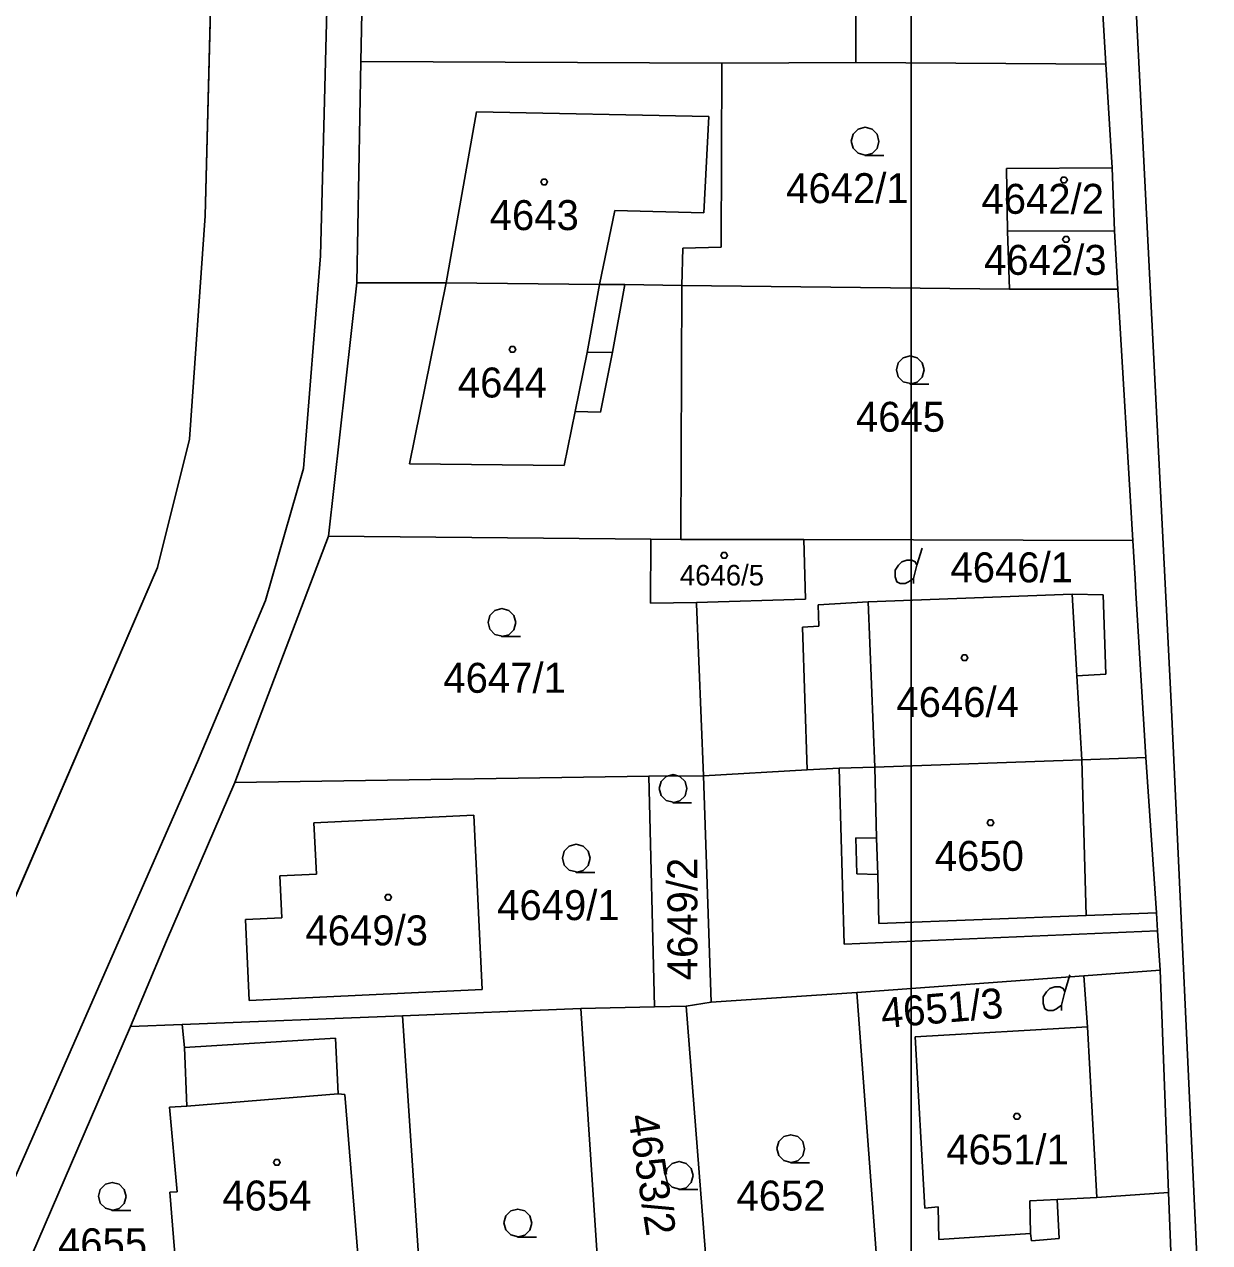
# Model space of a CAD drawing. Extents: x -263587 to -261993, y -1238795 to -1236748.
# Drawn here: x -262742.4 to -262679.1, y -1237619.9 to -1237554.8 of the extents above; entities that cross this region are included whole.
import ezdxf

# ---------------------------------------------------------------- set-up
doc = ezdxf.new("R2010")
doc.units = 0
for name, color, linetype in [('Vrstva 1', 7, 'Continuous'), ('Vrstva 2', 7, 'Continuous'), ('Vrstva 3', 7, 'Continuous'), ('Vrstva 51', 7, 'Continuous')]:
    doc.layers.add(name, color=color, linetype=linetype)

msp = doc.modelspace()

# ---------------------------------------------------------------- linework, layer by layer
at = {"layer": 'Vrstva 1'}
for p, q in [((-262725.22, -1237515.08), (-262726.58, -1237567.18)), ((-262684.42, -1237526.68), (-262682.75, -1237559.3)), ((-262685.72, -1237539.5), (-262684.63, -1237556.95)), ((-262684.63, -1237556.95), (-262685.72, -1237539.5)), ((-262724.42, -1237556.81), (-262724.09, -1237539.86)), ((-262724.09, -1237539.86), (-262724.42, -1237556.81)), ((-262732.74, -1237565.04), (-262732.21, -1237544.17)), ((-262732.21, -1237544.17), (-262732.74, -1237565.04)), ((-262697.98, -1237556.86), (-262697.99, -1237549)), ((-262697.99, -1237549), (-262697.98, -1237556.86)), ((-262724.64, -1237568.62), (-262724.42, -1237556.81)), ((-262724.42, -1237556.81), (-262724.64, -1237568.62)), ((-262705.15, -1237556.89), (-262724.42, -1237556.81)), ((-262724.42, -1237556.81), (-262705.15, -1237556.89)), ((-262705.18, -1237566.72), (-262705.15, -1237556.89)), ((-262705.15, -1237556.89), (-262705.18, -1237566.72)), ((-262705.15, -1237556.89), (-262697.98, -1237556.86)), ((-262697.98, -1237556.86), (-262705.15, -1237556.89)), ((-262684.63, -1237556.95), (-262697.98, -1237556.86)), ((-262697.98, -1237556.86), (-262684.63, -1237556.95)), ((-262684.63, -1237556.95), (-262684.29, -1237562.48)), ((-262684.29, -1237562.48), (-262684.63, -1237556.95)), ((-262682.75, -1237559.3), (-262681.14, -1237591.03)), ((-262718.25, -1237559.49), (-262719.87, -1237568.62)), ((-262705.83, -1237559.74), (-262718.25, -1237559.49)), ((-262706.1, -1237564.89), (-262705.83, -1237559.74)), ((-262689.94, -1237562.52), (-262684.29, -1237562.48)), ((-262684.29, -1237562.48), (-262689.94, -1237562.52)), ((-262689.89, -1237565.87), (-262689.94, -1237562.52)), ((-262689.94, -1237562.52), (-262689.89, -1237565.87)), ((-262684.29, -1237562.48), (-262684.17, -1237565.85)), ((-262684.17, -1237565.85), (-262684.29, -1237562.48)), ((-262733.58, -1237576.98), (-262732.74, -1237565.04)), ((-262732.74, -1237565.04), (-262733.58, -1237576.98)), ((-262711.67, -1237568.71), (-262710.85, -1237564.77)), ((-262710.85, -1237564.77), (-262706.1, -1237564.89)), ((-262689.89, -1237565.87), (-262684.17, -1237565.85)), ((-262684.17, -1237565.85), (-262689.89, -1237565.87)), ((-262689.78, -1237568.97), (-262689.89, -1237565.87)), ((-262689.89, -1237565.87), (-262689.78, -1237568.97)), ((-262684.17, -1237565.85), (-262683.99, -1237568.97)), ((-262683.99, -1237568.97), (-262684.17, -1237565.85)), ((-262707.28, -1237568.76), (-262707.23, -1237566.78)), ((-262707.23, -1237566.78), (-262707.28, -1237568.76)), ((-262707.23, -1237566.78), (-262705.18, -1237566.72)), ((-262705.18, -1237566.72), (-262707.23, -1237566.78)), ((-262726.58, -1237567.18), (-262727.48, -1237578.54)), ((-262726.16, -1237582.16), (-262724.64, -1237568.62)), ((-262724.64, -1237568.62), (-262726.16, -1237582.16)), ((-262724.64, -1237568.62), (-262719.87, -1237568.62)), ((-262719.87, -1237568.62), (-262724.64, -1237568.62)), ((-262719.87, -1237568.62), (-262721.82, -1237578.3)), ((-262719.87, -1237568.62), (-262711.67, -1237568.71)), ((-262711.67, -1237568.71), (-262719.87, -1237568.62)), ((-262711.67, -1237568.71), (-262712.33, -1237572.34)), ((-262711.67, -1237568.71), (-262710.33, -1237568.72)), ((-262710.33, -1237568.72), (-262711.67, -1237568.71)), ((-262710.33, -1237568.72), (-262710.99, -1237572.32)), ((-262710.33, -1237568.72), (-262707.28, -1237568.76)), ((-262707.28, -1237568.76), (-262710.33, -1237568.72)), ((-262707.33, -1237582.33), (-262707.28, -1237568.76)), ((-262707.28, -1237568.76), (-262707.33, -1237582.33)), ((-262707.28, -1237568.76), (-262689.78, -1237568.97)), ((-262689.78, -1237568.97), (-262707.28, -1237568.76)), ((-262689.78, -1237568.97), (-262683.99, -1237568.97)), ((-262683.99, -1237568.97), (-262689.78, -1237568.97)), ((-262683.99, -1237568.97), (-262683.19, -1237582.38)), ((-262683.19, -1237582.38), (-262683.99, -1237568.97)), ((-262712.33, -1237572.34), (-262710.99, -1237572.32)), ((-262710.99, -1237572.32), (-262711.62, -1237575.53)), ((-262712.98, -1237575.49), (-262712.33, -1237572.34)), ((-262713.56, -1237578.39), (-262712.98, -1237575.49)), ((-262711.62, -1237575.53), (-262712.98, -1237575.49)), ((-262735.28, -1237583.83), (-262733.58, -1237576.98)), ((-262733.58, -1237576.98), (-262735.28, -1237583.83)), ((-262727.48, -1237578.54), (-262729.52, -1237585.6)), ((-262721.82, -1237578.3), (-262713.56, -1237578.39)), ((-262726.16, -1237582.16), (-262731.16, -1237595.31)), ((-262731.16, -1237595.31), (-262726.16, -1237582.16)), ((-262708.93, -1237582.32), (-262726.16, -1237582.16)), ((-262726.16, -1237582.16), (-262708.93, -1237582.32)), ((-262708.93, -1237582.32), (-262708.96, -1237585.73)), ((-262708.96, -1237585.73), (-262708.93, -1237582.32)), ((-262707.33, -1237582.33), (-262708.93, -1237582.32)), ((-262708.93, -1237582.32), (-262707.33, -1237582.33)), ((-262706.63, -1237582.33), (-262707.33, -1237582.33)), ((-262707.33, -1237582.33), (-262706.63, -1237582.33)), ((-262700.76, -1237582.34), (-262706.63, -1237582.33)), ((-262706.63, -1237582.33), (-262700.76, -1237582.34)), ((-262683.19, -1237582.38), (-262700.76, -1237582.34)), ((-262700.67, -1237585.52), (-262700.76, -1237582.34)), ((-262700.76, -1237582.34), (-262683.19, -1237582.38)), ((-262700.76, -1237582.34), (-262700.67, -1237585.52)), ((-262683.07, -1237584.44), (-262683.19, -1237582.38)), ((-262683.19, -1237582.38), (-262683.07, -1237584.44)), ((-262694.72, -1237583.7), (-262694.45, -1237582.8)), ((-262745.26, -1237606.9), (-262735.28, -1237583.83)), ((-262735.28, -1237583.83), (-262745.26, -1237606.9)), ((-262683.03, -1237585.18), (-262683.07, -1237584.44)), ((-262683.07, -1237584.44), (-262683.03, -1237585.18)), ((-262697.33, -1237585.67), (-262686.43, -1237585.26)), ((-262686.43, -1237585.26), (-262697.33, -1237585.67)), ((-262686.43, -1237585.26), (-262684.78, -1237585.28)), ((-262684.78, -1237585.28), (-262686.43, -1237585.26)), ((-262686.43, -1237585.26), (-262686.18, -1237589.62)), ((-262684.78, -1237585.28), (-262684.63, -1237589.53)), ((-262684.63, -1237589.53), (-262684.78, -1237585.28)), ((-262682.49, -1237593.98), (-262683.03, -1237585.18)), ((-262683.03, -1237585.18), (-262682.49, -1237593.98)), ((-262729.52, -1237585.6), (-262733.15, -1237594.2)), ((-262708.96, -1237585.73), (-262706.49, -1237585.69)), ((-262706.49, -1237585.69), (-262708.96, -1237585.73)), ((-262706.49, -1237585.69), (-262700.67, -1237585.52)), ((-262700.67, -1237585.52), (-262706.49, -1237585.69)), ((-262706.49, -1237585.77), (-262706.49, -1237585.69)), ((-262706.49, -1237585.69), (-262706.49, -1237585.77)), ((-262706.13, -1237594.95), (-262706.49, -1237585.77)), ((-262706.49, -1237585.77), (-262706.13, -1237594.95)), ((-262700, -1237585.82), (-262697.33, -1237585.67)), ((-262697.33, -1237585.67), (-262700, -1237585.82)), ((-262699.97, -1237586.97), (-262700, -1237585.82)), ((-262700, -1237585.82), (-262699.97, -1237586.97)), ((-262697.33, -1237585.67), (-262696.98, -1237594.49)), ((-262700.84, -1237587.01), (-262699.97, -1237586.97)), ((-262699.97, -1237586.97), (-262700.84, -1237587.01)), ((-262700.59, -1237594.64), (-262700.84, -1237587.01)), ((-262700.84, -1237587.01), (-262700.59, -1237594.64)), ((-262684.63, -1237589.53), (-262686.18, -1237589.62)), ((-262686.18, -1237589.62), (-262684.63, -1237589.53)), ((-262686.18, -1237589.62), (-262685.92, -1237594.1)), ((-262685.92, -1237594.1), (-262686.18, -1237589.62)), ((-262681.14, -1237591.03), (-262679.09, -1237635.62)), ((-262733.15, -1237594.2), (-262745.42, -1237622.14)), ((-262696.98, -1237594.49), (-262685.92, -1237594.1)), ((-262685.92, -1237594.1), (-262696.98, -1237594.49)), ((-262685.92, -1237594.1), (-262682.49, -1237593.98)), ((-262682.49, -1237593.98), (-262685.92, -1237594.1)), ((-262685.92, -1237594.1), (-262685.69, -1237602.42)), ((-262682.49, -1237593.98), (-262681.93, -1237602.28)), ((-262681.93, -1237602.28), (-262682.49, -1237593.98)), ((-262731.16, -1237595.31), (-262709.04, -1237594.97)), ((-262709.04, -1237594.97), (-262731.16, -1237595.31)), ((-262709.04, -1237594.97), (-262706.13, -1237594.95)), ((-262706.13, -1237594.95), (-262709.04, -1237594.97)), ((-262709.04, -1237594.97), (-262708.74, -1237607.3)), ((-262708.74, -1237607.3), (-262709.04, -1237594.97)), ((-262706.13, -1237594.95), (-262700.59, -1237594.64)), ((-262700.59, -1237594.64), (-262706.13, -1237594.95)), ((-262705.72, -1237607.05), (-262706.13, -1237594.95)), ((-262706.13, -1237594.95), (-262705.72, -1237607.05)), ((-262700.59, -1237594.64), (-262698.87, -1237594.55)), ((-262698.87, -1237594.55), (-262700.59, -1237594.64)), ((-262698.87, -1237594.55), (-262696.98, -1237594.49)), ((-262696.98, -1237594.49), (-262698.87, -1237594.55)), ((-262698.61, -1237603.95), (-262698.87, -1237594.55)), ((-262696.98, -1237594.49), (-262696.88, -1237598.29)), ((-262731.16, -1237595.31), (-262734.81, -1237603.76)), ((-262734.81, -1237603.76), (-262731.16, -1237595.31)), ((-262718.39, -1237597.05), (-262726.93, -1237597.46)), ((-262726.93, -1237597.46), (-262718.39, -1237597.05)), ((-262717.94, -1237606.36), (-262718.39, -1237597.05)), ((-262718.39, -1237597.05), (-262717.94, -1237606.36)), ((-262726.93, -1237597.46), (-262726.8, -1237600.2)), ((-262726.8, -1237600.2), (-262726.93, -1237597.46)), ((-262697.94, -1237600.19), (-262697.98, -1237598.27)), ((-262697.98, -1237598.27), (-262696.88, -1237598.29)), ((-262696.88, -1237598.29), (-262696.82, -1237600.22)), ((-262726.8, -1237600.2), (-262728.75, -1237600.29)), ((-262728.75, -1237600.29), (-262726.8, -1237600.2)), ((-262728.75, -1237600.29), (-262728.64, -1237602.54)), ((-262728.64, -1237602.54), (-262728.75, -1237600.29)), ((-262696.82, -1237600.22), (-262697.94, -1237600.19)), ((-262696.82, -1237600.22), (-262696.75, -1237602.85)), ((-262728.64, -1237602.54), (-262730.59, -1237602.63)), ((-262730.59, -1237602.63), (-262728.64, -1237602.54)), ((-262730.59, -1237602.63), (-262730.39, -1237606.96)), ((-262730.39, -1237606.96), (-262730.59, -1237602.63)), ((-262696.75, -1237602.85), (-262685.69, -1237602.42)), ((-262685.69, -1237602.42), (-262681.93, -1237602.28)), ((-262681.93, -1237602.28), (-262681.87, -1237603.23)), ((-262681.87, -1237603.23), (-262681.93, -1237602.28)), ((-262681.87, -1237603.23), (-262698.61, -1237603.95)), ((-262681.87, -1237603.23), (-262681.73, -1237605.33)), ((-262681.73, -1237605.33), (-262681.87, -1237603.23)), ((-262734.81, -1237603.76), (-262736.72, -1237608.35)), ((-262736.72, -1237608.35), (-262734.81, -1237603.76)), ((-262681.73, -1237605.33), (-262685.81, -1237605.63)), ((-262685.81, -1237605.63), (-262681.73, -1237605.33)), ((-262681.73, -1237605.33), (-262681.28, -1237617.21)), ((-262681.28, -1237617.21), (-262681.73, -1237605.33)), ((-262685.81, -1237605.63), (-262697.94, -1237606.53)), ((-262697.94, -1237606.53), (-262685.81, -1237605.63)), ((-262686.82, -1237606.49), (-262686.55, -1237605.59)), ((-262685.62, -1237608.36), (-262685.81, -1237605.63)), ((-262730.39, -1237606.96), (-262717.94, -1237606.36)), ((-262717.94, -1237606.36), (-262730.39, -1237606.96)), ((-262697.94, -1237606.53), (-262705.72, -1237607.05)), ((-262705.72, -1237607.05), (-262697.94, -1237606.53)), ((-262696.5, -1237625.67), (-262697.94, -1237606.53)), ((-262697.94, -1237606.53), (-262696.5, -1237625.67)), ((-262722.2, -1237607.78), (-262712.67, -1237607.38)), ((-262712.67, -1237607.38), (-262722.2, -1237607.78)), ((-262712.67, -1237607.38), (-262708.74, -1237607.3)), ((-262708.74, -1237607.3), (-262712.67, -1237607.38)), ((-262712.67, -1237607.38), (-262711.37, -1237627.29)), ((-262711.37, -1237627.29), (-262712.67, -1237607.38)), ((-262708.74, -1237607.3), (-262707.05, -1237607.25)), ((-262707.05, -1237607.25), (-262708.74, -1237607.3)), ((-262707.05, -1237607.25), (-262705.72, -1237607.05)), ((-262705.72, -1237607.05), (-262707.05, -1237607.25)), ((-262705.54, -1237626.61), (-262707.05, -1237607.25)), ((-262707.05, -1237607.25), (-262705.54, -1237626.61)), ((-262733.96, -1237608.23), (-262722.2, -1237607.78)), ((-262722.2, -1237607.78), (-262733.96, -1237608.23)), ((-262722.2, -1237607.78), (-262720.83, -1237628.38)), ((-262720.83, -1237628.38), (-262722.2, -1237607.78)), ((-262742.95, -1237622.74), (-262736.72, -1237608.35)), ((-262736.72, -1237608.35), (-262742.95, -1237622.74)), ((-262736.72, -1237608.35), (-262733.96, -1237608.23)), ((-262733.96, -1237608.23), (-262736.72, -1237608.35)), ((-262733.84, -1237609.46), (-262733.96, -1237608.23)), ((-262733.96, -1237608.23), (-262733.84, -1237609.46)), ((-262685.62, -1237608.36), (-262694.81, -1237608.89)), ((-262694.81, -1237608.89), (-262685.62, -1237608.36)), ((-262685.12, -1237617.47), (-262685.62, -1237608.36)), ((-262685.62, -1237608.36), (-262685.12, -1237617.47)), ((-262733.84, -1237609.46), (-262725.77, -1237608.97)), ((-262725.77, -1237608.97), (-262725.64, -1237611.94)), ((-262694.81, -1237608.89), (-262694.31, -1237618.04)), ((-262694.31, -1237618.04), (-262694.81, -1237608.89)), ((-262733.71, -1237612.59), (-262733.84, -1237609.46)), ((-262733.84, -1237609.46), (-262733.71, -1237612.59)), ((-262733.71, -1237612.59), (-262725.64, -1237611.94)), ((-262725.64, -1237611.94), (-262725.28, -1237611.97)), ((-262725.28, -1237611.97), (-262724.4, -1237622.64)), ((-262734.65, -1237612.65), (-262733.71, -1237612.59)), ((-262733.71, -1237612.59), (-262734.65, -1237612.65)), ((-262734.23, -1237617.17), (-262734.65, -1237612.65)), ((-262734.65, -1237612.65), (-262734.23, -1237617.17)), ((-262734.62, -1237617.19), (-262734.23, -1237617.17)), ((-262734.23, -1237617.17), (-262734.62, -1237617.19)), ((-262734.23, -1237622.09), (-262734.62, -1237617.19)), ((-262734.62, -1237617.19), (-262734.23, -1237622.09)), ((-262685.12, -1237617.47), (-262681.28, -1237617.21)), ((-262681.28, -1237617.21), (-262681.14, -1237620.81)), ((-262681.14, -1237620.81), (-262681.28, -1237617.21)), ((-262687.23, -1237617.59), (-262688.7, -1237617.66)), ((-262688.7, -1237617.66), (-262688.66, -1237619.39)), ((-262687.23, -1237617.59), (-262685.12, -1237617.47)), ((-262685.12, -1237617.47), (-262687.23, -1237617.59)), ((-262687.13, -1237619.66), (-262687.23, -1237617.59)), ((-262687.23, -1237617.59), (-262687.13, -1237619.66)), ((-262694.31, -1237618.04), (-262693.59, -1237617.97)), ((-262693.59, -1237617.97), (-262694.31, -1237618.04)), ((-262693.59, -1237617.97), (-262693.56, -1237619.72)), ((-262693.56, -1237619.72), (-262693.59, -1237617.97)), ((-262693.56, -1237619.72), (-262688.66, -1237619.39)), ((-262688.66, -1237619.39), (-262693.56, -1237619.72)), ((-262688.66, -1237619.39), (-262688.61, -1237619.79)), ((-262688.61, -1237619.79), (-262688.66, -1237619.39)), ((-262688.61, -1237619.79), (-262687.13, -1237619.66)), ((-262687.13, -1237619.66), (-262688.61, -1237619.79))]:
    msp.add_line(p, q, dxfattribs=at)
for points in [[(-262697.48, -1237561.8), (-262697.86, -1237561.7), (-262698.13, -1237561.43), (-262698.23, -1237561.06), (-262698.13, -1237560.69), (-262697.86, -1237560.42), (-262697.49, -1237560.32), (-262697.12, -1237560.42), (-262696.85, -1237560.69), (-262696.75, -1237561.07), (-262696.85, -1237561.45), (-262697.12, -1237561.72), (-262697.5, -1237561.82), (-262696.5, -1237561.82)], [(-262695.07, -1237574.01), (-262695.45, -1237573.91), (-262695.72, -1237573.64), (-262695.82, -1237573.27), (-262695.72, -1237572.9), (-262695.45, -1237572.63), (-262695.08, -1237572.53), (-262694.71, -1237572.63), (-262694.44, -1237572.9), (-262694.34, -1237573.28), (-262694.44, -1237573.66), (-262694.71, -1237573.93), (-262695.09, -1237574.03), (-262694.09, -1237574.03)], [(-262694.9, -1237584.69), (-262694.9, -1237584.42), (-262694.72, -1237583.7), (-262694.81, -1237583.52), (-262694.99, -1237583.43), (-262695.26, -1237583.43), (-262695.53, -1237583.52), (-262695.71, -1237583.7), (-262695.89, -1237583.97), (-262695.89, -1237584.33), (-262695.8, -1237584.6), (-262695.62, -1237584.69), (-262695.35, -1237584.69), (-262695.17, -1237584.6), (-262694.9, -1237584.42)], [(-262716.88, -1237587.5), (-262717.26, -1237587.4), (-262717.53, -1237587.13), (-262717.63, -1237586.76), (-262717.53, -1237586.39), (-262717.26, -1237586.12), (-262716.89, -1237586.02), (-262716.52, -1237586.12), (-262716.25, -1237586.39), (-262716.15, -1237586.77), (-262716.25, -1237587.15), (-262716.52, -1237587.42), (-262716.9, -1237587.52), (-262715.9, -1237587.52)], [(-262707.74, -1237596.37), (-262708.12, -1237596.27), (-262708.39, -1237596), (-262708.49, -1237595.63), (-262708.39, -1237595.26), (-262708.12, -1237594.99), (-262707.75, -1237594.89), (-262707.38, -1237594.99), (-262707.11, -1237595.26), (-262707.01, -1237595.64), (-262707.11, -1237596.02), (-262707.38, -1237596.29), (-262707.76, -1237596.39), (-262706.76, -1237596.39)], [(-262712.91, -1237600.09), (-262713.29, -1237599.99), (-262713.56, -1237599.72), (-262713.66, -1237599.35), (-262713.56, -1237598.98), (-262713.29, -1237598.71), (-262712.92, -1237598.61), (-262712.55, -1237598.71), (-262712.28, -1237598.98), (-262712.18, -1237599.36), (-262712.28, -1237599.74), (-262712.55, -1237600.01), (-262712.93, -1237600.11), (-262711.93, -1237600.11)], [(-262687, -1237607.48), (-262687, -1237607.21), (-262686.82, -1237606.49), (-262686.91, -1237606.31), (-262687.09, -1237606.22), (-262687.36, -1237606.22), (-262687.63, -1237606.31), (-262687.81, -1237606.49), (-262687.99, -1237606.76), (-262687.99, -1237607.12), (-262687.9, -1237607.39), (-262687.72, -1237607.48), (-262687.45, -1237607.48), (-262687.27, -1237607.39), (-262687, -1237607.21)], [(-262701.45, -1237615.6), (-262701.83, -1237615.5), (-262702.1, -1237615.23), (-262702.2, -1237614.86), (-262702.1, -1237614.49), (-262701.83, -1237614.22), (-262701.46, -1237614.12), (-262701.09, -1237614.22), (-262700.82, -1237614.49), (-262700.72, -1237614.87), (-262700.82, -1237615.25), (-262701.09, -1237615.52), (-262701.47, -1237615.62), (-262700.47, -1237615.62)], [(-262707.41, -1237617.03), (-262707.79, -1237616.93), (-262708.06, -1237616.66), (-262708.16, -1237616.29), (-262708.06, -1237615.92), (-262707.79, -1237615.65), (-262707.42, -1237615.55), (-262707.05, -1237615.65), (-262706.78, -1237615.92), (-262706.68, -1237616.3), (-262706.78, -1237616.68), (-262707.05, -1237616.95), (-262707.43, -1237617.05), (-262706.43, -1237617.05)], [(-262737.69, -1237618.15), (-262738.07, -1237618.05), (-262738.34, -1237617.78), (-262738.44, -1237617.41), (-262738.34, -1237617.04), (-262738.07, -1237616.77), (-262737.7, -1237616.67), (-262737.33, -1237616.77), (-262737.06, -1237617.04), (-262736.96, -1237617.42), (-262737.06, -1237617.8), (-262737.33, -1237618.07), (-262737.71, -1237618.17), (-262736.71, -1237618.17)], [(-262716.03, -1237619.57), (-262716.41, -1237619.47), (-262716.68, -1237619.2), (-262716.78, -1237618.83), (-262716.68, -1237618.46), (-262716.41, -1237618.19), (-262716.04, -1237618.09), (-262715.67, -1237618.19), (-262715.4, -1237618.46), (-262715.3, -1237618.84), (-262715.4, -1237619.22), (-262715.67, -1237619.49), (-262716.05, -1237619.59), (-262715.05, -1237619.59)]]:
    msp.add_lwpolyline(points, dxfattribs=at)
for points in [[(-262714.54, -1237563.09), (-262714.45, -1237563.24), (-262714.54, -1237563.39), (-262714.72, -1237563.39), (-262714.81, -1237563.24), (-262714.72, -1237563.09)], [(-262686.78, -1237562.98), (-262686.69, -1237563.13), (-262686.78, -1237563.28), (-262686.96, -1237563.28), (-262687.05, -1237563.13), (-262686.96, -1237562.98)], [(-262686.67, -1237566.16), (-262686.58, -1237566.31), (-262686.67, -1237566.46), (-262686.85, -1237566.46), (-262686.94, -1237566.31), (-262686.85, -1237566.16)], [(-262716.24, -1237572.03), (-262716.15, -1237572.18), (-262716.24, -1237572.33), (-262716.42, -1237572.33), (-262716.51, -1237572.18), (-262716.42, -1237572.03)], [(-262704.93, -1237583.03), (-262704.84, -1237583.18), (-262704.93, -1237583.33), (-262705.11, -1237583.33), (-262705.2, -1237583.18), (-262705.11, -1237583.03)], [(-262692.09, -1237588.5), (-262692, -1237588.65), (-262692.09, -1237588.8), (-262692.27, -1237588.8), (-262692.36, -1237588.65), (-262692.27, -1237588.5)], [(-262690.7, -1237597.31), (-262690.61, -1237597.46), (-262690.7, -1237597.61), (-262690.88, -1237597.61), (-262690.97, -1237597.46), (-262690.88, -1237597.31)], [(-262722.87, -1237601.29), (-262722.78, -1237601.44), (-262722.87, -1237601.59), (-262723.05, -1237601.59), (-262723.14, -1237601.44), (-262723.05, -1237601.29)], [(-262689.29, -1237612.99), (-262689.2, -1237613.14), (-262689.29, -1237613.29), (-262689.47, -1237613.29), (-262689.56, -1237613.14), (-262689.47, -1237612.99)], [(-262728.82, -1237615.45), (-262728.73, -1237615.6), (-262728.82, -1237615.75), (-262729, -1237615.75), (-262729.09, -1237615.6), (-262729, -1237615.45)]]:
    msp.add_lwpolyline(points, close=True, dxfattribs=at)
at = {"layer": 'Vrstva 2'}
msp.add_lwpolyline([(-262753.33, -1237625.635), (-262745.26, -1237606.9), (-262735.28, -1237583.83), (-262733.58, -1237576.98), (-262732.74, -1237565.04), (-262732.21, -1237544.17), (-262731.39, -1237511.76), (-262730.95, -1237461.27), (-262730.63, -1237425.62), (-262730.13, -1237378.82), (-262729.58, -1237341.73), (-262728.955, -1237306.535), (-262728.75, -1237298.15)], dxfattribs=at)
at = {"layer": 'Vrstva 3'}
msp.add_lwpolyline([(-262744.25, -1237230.5), (-262727.51, -1237252.7), (-262720.535, -1237260.115), (-262719.819, -1237263.32), (-262725.18, -1237264.54), (-262731.17, -1237266.01), (-262730.23, -1237271.65), (-262726.66, -1237279.47), (-262728.52, -1237280.61), (-262728.56, -1237282.52), (-262728.73, -1237295.74), (-262728.75, -1237298.15), (-262729.16, -1237314.92), (-262729.45, -1237331.3), (-262729.71, -1237352.16), (-262730.55, -1237405.48), (-262730.82, -1237444.8), (-262731.08, -1237477.74), (-262731.39, -1237511.76), (-262732.21, -1237544.17), (-262732.74, -1237565.04), (-262733.58, -1237576.98), (-262735.28, -1237583.83), (-262745.26, -1237606.9)], dxfattribs=at)
at = {"layer": 'Vrstva 51'}
msp.add_lwpolyline([(-262992.03, -1237088.09), (-262695.03, -1237088.09), (-262695.03, -1238768.09), (-262992.03, -1238768.09)], close=True, dxfattribs=at)

# ---------------------------------------------------------------- texts
at = {"layer": 'Vrstva 1'}
for s, height, p in [('4642/1', 1.6, (-262701.708, -1237564.37)), ('4642/2', 1.6, (-262691.277, -1237564.94)), ('4643', 1.6, (-262717.542, -1237565.81)), ('4642/3', 1.6, (-262691.137, -1237568.2)), ('4644', 1.6, (-262719.242, -1237574.75)), ('4645', 1.6, (-262697.982, -1237576.58)), ('4646/1', 1.6, (-262692.932, -1237584.62)), ('4646/5', 1.1, (-262707.388, -1237584.79)), ('4647/1', 1.6, (-262720.018, -1237590.52)), ('4646/4', 1.6, (-262695.821, -1237591.81)), ('4650', 1.6, (-262693.771, -1237600.03)), ('4649/1', 1.6, (-262717.144, -1237602.66)), ('4649/3', 1.6, (-262727.383, -1237604.01)), ('4651/1', 1.6, (-262693.155, -1237615.71)), ('4654', 1.6, (-262731.822, -1237618.17)), ('4652', 1.6, (-262704.362, -1237618.17)), ('4655', 1.6, (-262740.602, -1237620.72))]:
    msp.add_text(s, height=height, dxfattribs=at).set_placement(p)
for s, rotation, p in [('4649/2', 90.01167, (-262706.449, -1237605.873)), ('4651/3', 4.98473, (-262696.581, -1237608.436)), ('4653/2', 278.80126, (-262710.157, -1237613.127))]:
    msp.add_text(s, height=1.6, rotation=rotation, dxfattribs=at).set_placement(p)

doc.saveas('drawing.dxf')
